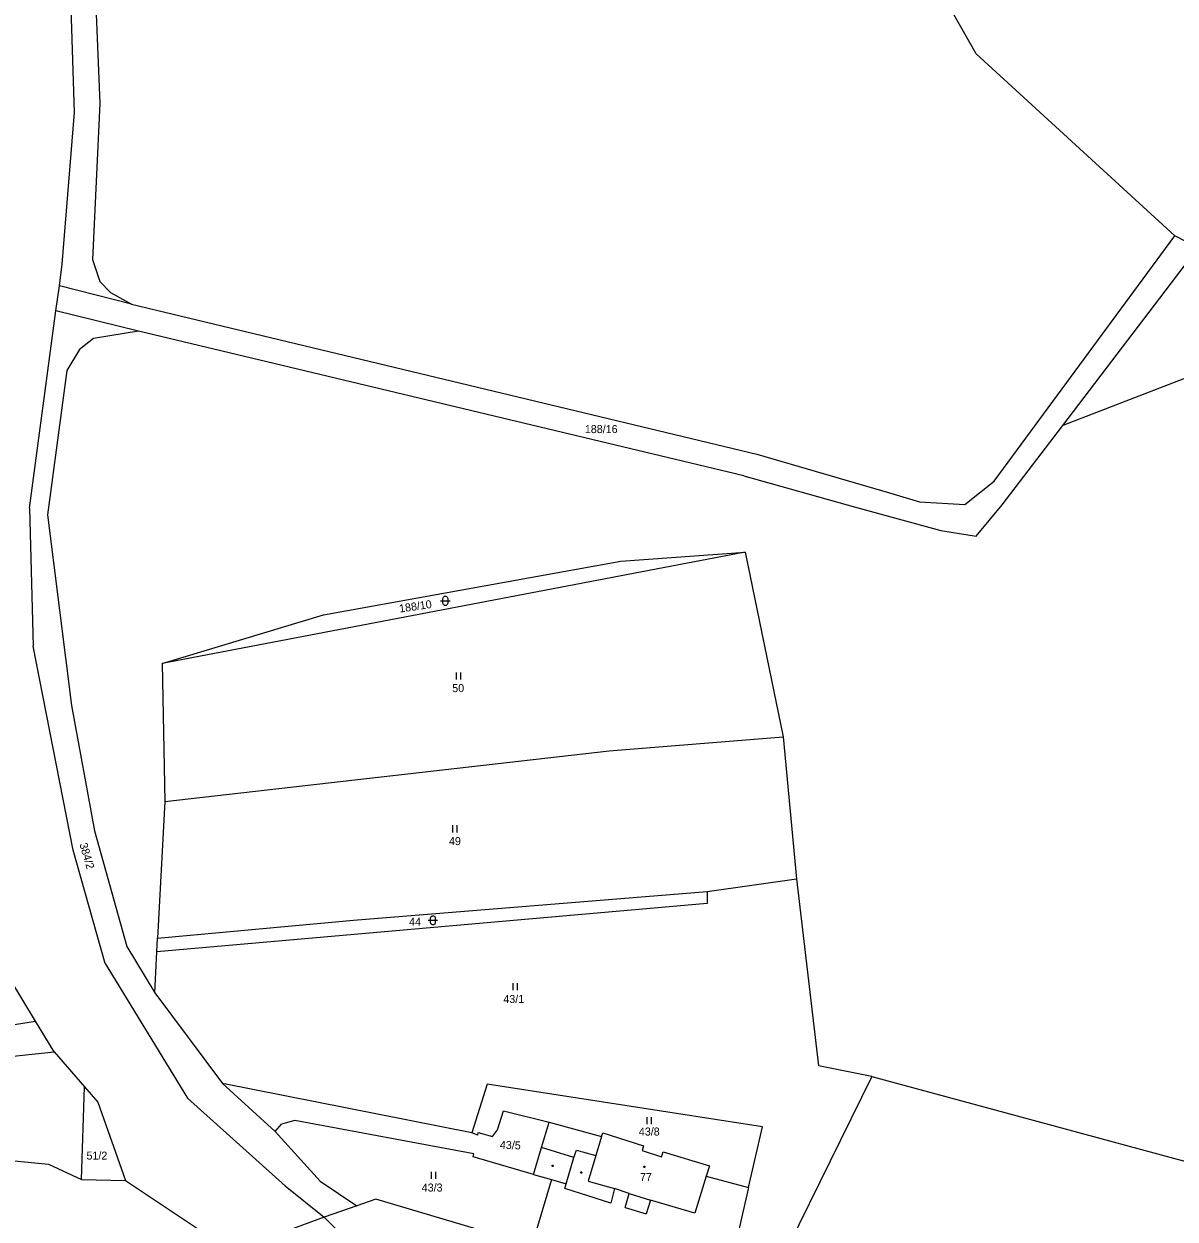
# Model space of a CAD drawing. Extents: x -811039 to -805820, y -1161436 to -1155864.
# Drawn here: x -806536.9 to -806292.6, y -1157981.5 to -1157727.6 of the extents above; entities that cross this region are included whole.
import ezdxf

# ---------------------------------------------------------------- set-up
doc = ezdxf.new("R2010")
doc.units = 0
for name, color, linetype in [('Default', 7, 'Continuous'), ('Hranice kat_území', 7, 'Continuous'), ('Hranice parcel', 7, 'Continuous'), ('Parcelní čísla', 7, 'Continuous'), ('Vnitřní kresba', 7, 'Continuous'), ('Značky budov', 7, 'Continuous'), ('Značky kultur', 7, 'Continuous')]:
    doc.layers.add(name, color=color, linetype=linetype)

# ---------------------------------------------------------------- blocks, each defined once
blk = doc.blocks.new('306')
at = {"layer": 'Default'}
for p, q in [((-0.5, 1.5), (-0.5, 0)), ((0.5, 0), (0.5, 1.5))]:
    blk.add_line(p, q, dxfattribs=at)
blk = doc.blocks.new('316')
at = {"layer": 'Default'}
for points in [[(-1, 1), (0.27, 1), (1, 1)], [(-0.5, 1.5), (-0.4, 1.79), (-0.15, 1.97), (0.16, 1.97), (0.41, 1.79), (0.51, 1.5), (0.51, 0.5), (0.41, 0.21), (0.16, 0.03), (-0.15, 0.03), (-0.4, 0.21), (-0.5, 0.5), (-0.5, 1.5)]]:
    blk.add_lwpolyline(points, dxfattribs=at)
blk = doc.blocks.new('402')
at = {"layer": 'Default'}
blk.add_lwpolyline([(0.09, 0.15), (0.18, 0), (0.09, -0.15), (-0.09, -0.15), (-0.18, 0), (-0.09, 0.15), (0.09, 0.15)], dxfattribs=at)

msp = doc.modelspace()

# ---------------------------------------------------------------- linework, layer by layer
at = {"layer": 'Hranice kat_území'}
for p, q in [((-806334.8, -1157733.98), (-806369.85, -1157671.95)), ((-806292.59, -1157772.68), (-806334.8, -1157733.98)), ((-806287.65, -1157775.18), (-806292.59, -1157772.68))]:
    msp.add_line(p, q, dxfattribs=at)
at = {"layer": 'Hranice parcel'}
for p, q in [((-806526.14, -1157746.49), (-806527.36, -1157709)), ((-806522.05, -1157712.53), (-806520.82, -1157744.55)), ((-806528.76, -1157778.68), (-806526.14, -1157746.49)), ((-806520.82, -1157744.55), (-806522.31, -1157777.7)), ((-806330.97, -1157824.79), (-806292.59, -1157772.68)), ((-806316.4, -1157812.94), (-806287.65, -1157775.18)), ((-806529.38, -1157783.31), (-806528.76, -1157778.68)), ((-806522.31, -1157777.7), (-806520.78, -1157782.33)), ((-806530.09, -1157788.59), (-806529.38, -1157783.31)), ((-806514.04, -1157787.19), (-806529.38, -1157783.31)), ((-806520.78, -1157782.33), (-806518.52, -1157784.69)), ((-806518.52, -1157784.69), (-806514.04, -1157787.19)), ((-806514.04, -1157787.19), (-806381.37, -1157819.05)), ((-806535.68, -1157830.51), (-806530.09, -1157788.59)), ((-806512.61, -1157792.88), (-806530.09, -1157788.59)), ((-806257.74, -1157790.3), (-806316.4, -1157812.94)), ((-806522.14, -1157794.46), (-806525.1, -1157796.8)), ((-806512.61, -1157792.88), (-806522.14, -1157794.46)), ((-806384.1, -1157823.65), (-806512.61, -1157792.88)), ((-806525.1, -1157796.8), (-806527.8, -1157801.25)), ((-806527.8, -1157801.25), (-806531.86, -1157831.91)), ((-806329.24, -1157829.81), (-806316.4, -1157812.94)), ((-806381.37, -1157819.05), (-806353.2, -1157827.23)), ((-806384.1, -1157823.65), (-806360.37, -1157830.3)), ((-806337.22, -1157829.69), (-806330.97, -1157824.79)), ((-806353.2, -1157827.23), (-806346.79, -1157829.18)), ((-806360.37, -1157830.3), (-806342.28, -1157835.26)), ((-806346.79, -1157829.18), (-806337.22, -1157829.69)), ((-806334.75, -1157836.41), (-806329.24, -1157829.81)), ((-806535.68, -1157830.51), (-806534.91, -1157859.83)), ((-806531.86, -1157831.91), (-806526.83, -1157872.37)), ((-806342.28, -1157835.26), (-806334.75, -1157836.41)), ((-806383.79, -1157839.85), (-806507.59, -1157863.46)), ((-806410.21, -1157841.74), (-806383.79, -1157839.85)), ((-806383.79, -1157839.85), (-806375.72, -1157879.06)), ((-806473.34, -1157853.13), (-806410.21, -1157841.74)), ((-806507.59, -1157863.46), (-806473.34, -1157853.13)), ((-806526.44, -1157903.12), (-806534.91, -1157859.83)), ((-806507.59, -1157863.46), (-806507.02, -1157892.82)), ((-806526.83, -1157872.37), (-806521.94, -1157899)), ((-806412.71, -1157882), (-806375.72, -1157879.06)), ((-806375.72, -1157879.06), (-806372.94, -1157909.21)), ((-806507.02, -1157892.82), (-806412.71, -1157882)), ((-806507.02, -1157892.82), (-806508.53, -1157921.81)), ((-806521.94, -1157899), (-806515.04, -1157923.58)), ((-806519.66, -1157927.16), (-806526.44, -1157903.12)), ((-806391.9, -1157911.93), (-806372.94, -1157909.21)), ((-806372.94, -1157909.21), (-806368.28, -1157948.94)), ((-806466.96, -1157918.01), (-806391.9, -1157911.93)), ((-806391.9, -1157911.93), (-806391.88, -1157914.43)), ((-806391.88, -1157914.43), (-806508.67, -1157924.72)), ((-806534.45, -1157939.44), (-806547.36, -1157918.12)), ((-806508.53, -1157921.81), (-806466.96, -1157918.01)), ((-806515.04, -1157923.58), (-806509.08, -1157933.39)), ((-806508.67, -1157924.72), (-806508.53, -1157921.81)), ((-806509.08, -1157933.39), (-806508.67, -1157924.72)), ((-806519.66, -1157927.16), (-806502.17, -1157955.78)), ((-806509.08, -1157933.39), (-806494.73, -1157952.71)), ((-806573.34, -1157945.48), (-806534.45, -1157939.44)), ((-806530.51, -1157945.95), (-806534.45, -1157939.44)), ((-806553.43, -1157948.32), (-806530.51, -1157945.95)), ((-806530.51, -1157945.95), (-806524.04, -1157953.41)), ((-806356.95, -1157951.21), (-806368.28, -1157948.94)), ((-806356.95, -1157951.21), (-806381.62, -1158001.34)), ((-806356.95, -1157951.21), (-806280.78, -1157971.8)), ((-806524.69, -1157973.05), (-806524.04, -1157953.41)), ((-806524.04, -1157953.41), (-806521.21, -1157956.67)), ((-806441.82, -1157963.17), (-806494.73, -1157952.71)), ((-806494.73, -1157952.71), (-806483.6, -1157962.9)), ((-806438.6, -1157952.82), (-806441.82, -1157963.17)), ((-806380.1, -1157961.87), (-806438.6, -1157952.82)), ((-806521.21, -1157956.67), (-806515.35, -1157973.25)), ((-806502.17, -1157955.78), (-806481.48, -1157974.4)), ((-806436.4, -1157962.49), (-806435.1, -1157958.46)), ((-806435.1, -1157958.46), (-806425.42, -1157960.91)), ((-806483.6, -1157962.9), (-806482.26, -1157961.34)), ((-806479.4, -1157960.55), (-806482.26, -1157961.34)), ((-806441.41, -1157967.64), (-806479.4, -1157960.55)), ((-806427.05, -1157966.25), (-806425.42, -1157960.91)), ((-806425.42, -1157960.91), (-806414.28, -1157963.91)), ((-806383.1, -1157974.77), (-806380.1, -1157961.87)), ((-806483.6, -1157962.9), (-806473.99, -1157973.45)), ((-806440.58, -1157963.65), (-806441.82, -1157963.17)), ((-806440.58, -1157963.65), (-806440.48, -1157963.1)), ((-806440.48, -1157963.1), (-806437.43, -1157963.91)), ((-806437.43, -1157963.91), (-806436.4, -1157962.49)), ((-806414.28, -1157963.91), (-806414.05, -1157963.19)), ((-806414.05, -1157963.19), (-806405.36, -1157965.91)), ((-806428.74, -1157971.97), (-806427.05, -1157966.25)), ((-806405.36, -1157965.91), (-806405.64, -1157966.93)), ((-806405.64, -1157966.93), (-806401.56, -1157968.23)), ((-806401.56, -1157968.23), (-806401.24, -1157967.18)), ((-806401.24, -1157967.18), (-806391.41, -1157970.14)), ((-806541.08, -1157968.88), (-806531.68, -1157969.79)), ((-806531.68, -1157969.79), (-806524.69, -1157973.05)), ((-806441.54, -1157968.22), (-806441.41, -1157967.64)), ((-806428.74, -1157971.97), (-806441.54, -1157968.22)), ((-806428.74, -1157971.97), (-806424.9, -1157973.07)), ((-806392.12, -1157972.38), (-806394.53, -1157980.23)), ((-806391.41, -1157970.14), (-806392.12, -1157972.38)), ((-806392.12, -1157972.38), (-806383.1, -1157974.77)), ((-806524.69, -1157973.05), (-806515.35, -1157973.25)), ((-806515.35, -1157973.25), (-806497.28, -1157985.34)), ((-806481.48, -1157974.4), (-806473.17, -1157981.08)), ((-806473.99, -1157973.45), (-806466.25, -1157978.68)), ((-806424.9, -1157973.07), (-806429.06, -1157987.06)), ((-806424.9, -1157973.07), (-806421.84, -1157973.96)), ((-806422.11, -1157975.01), (-806421.84, -1157973.96)), ((-806412.34, -1157978.08), (-806422.11, -1157975.01)), ((-806411.53, -1157974.97), (-806412.34, -1157978.08)), ((-806408.41, -1157976.03), (-806411.53, -1157974.97)), ((-806383.1, -1157974.77), (-806388.68, -1157998.88)), ((-806462.21, -1157977.22), (-806466.25, -1157978.68)), ((-806429.06, -1157987.06), (-806462.21, -1157977.22)), ((-806409.28, -1157979.02), (-806408.41, -1157976.03)), ((-806403.94, -1157977.42), (-806404.81, -1157980.34)), ((-806394.53, -1157980.23), (-806403.94, -1157977.42)), ((-806466.25, -1157978.68), (-806473.17, -1157981.08)), ((-806409.28, -1157979.02), (-806404.81, -1157980.34)), ((-806473.17, -1157981.08), (-806492.48, -1157988.16)), ((-806473.17, -1157981.08), (-806466.66, -1157987.53))]:
    msp.add_line(p, q, dxfattribs=at)
at = {"layer": 'Vnitřní kresba'}
for p, q in [((-806414.28, -1157963.91), (-806415.51, -1157967.95)), ((-806420.16, -1157968.41), (-806427.05, -1157966.25)), ((-806420.16, -1157968.41), (-806419.62, -1157966.81)), ((-806419.62, -1157966.81), (-806415.51, -1157967.95)), ((-806421.84, -1157973.96), (-806420.16, -1157968.41)), ((-806415.51, -1157967.95), (-806417.12, -1157973.4)), ((-806417.12, -1157973.4), (-806411.53, -1157974.97)), ((-806408.41, -1157976.03), (-806403.94, -1157977.42))]:
    msp.add_line(p, q, dxfattribs=at)

# ---------------------------------------------------------------- block references
at = {"layer": 'Značky budov'}
for p in [(-806424.69, -1157970.17), (-806418.61, -1157971.6), (-806405.23, -1157970.36)]:
    msp.add_blockref('402', p, dxfattribs=at)
at = {"layer": 'Značky kultur'}
for name, p in [('316', (-806447.45, -1157851.17)), ('306', (-806444.65, -1157866.86)), ('306', (-806445.43, -1157899.35)), ('316', (-806450.09, -1157919.02)), ('306', (-806432.66, -1157932.88)), ('306', (-806404.16, -1157961.34)), ('306', (-806449.98, -1157972.93))]:
    msp.add_blockref(name, p, dxfattribs=at)

# ---------------------------------------------------------------- texts
at = {"layer": 'Parcelní čísla'}
for s, p in [('188/16', (-806417.84, -1157814.55)), ('50', (-806445.99, -1157869.56)), ('49', (-806446.69, -1157902.05)), ('44', (-806455.15, -1157919.19)), ('43/1', (-806435.14, -1157935.58)), ('43/8', (-806406.38, -1157963.73)), ('51/2', (-806523.62, -1157968.84)), ('77', (-806406.14, -1157973.38)), ('43/3', (-806452.46, -1157975.62))]:
    msp.add_text(s, height=1.7, dxfattribs=at).set_placement(p)
for s, rotation, p in [('188/10', 8.365, (-806457.13, -1157852.68)), ('384/2', 286.536, (-806525.14, -1157901.86)), ('43/5', 357.984, (-806435.9, -1157966.53))]:
    msp.add_text(s, height=1.7, rotation=rotation, dxfattribs=at).set_placement(p)

doc.saveas('drawing.dxf')
